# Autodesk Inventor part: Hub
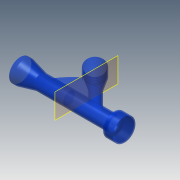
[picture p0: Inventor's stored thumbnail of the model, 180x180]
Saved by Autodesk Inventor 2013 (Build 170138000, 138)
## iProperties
Created: 2013-11
Part Number: Hub
Material: Polycarbonate, Clear
Document SubType Name: Modeling
Designer: Warren
Density: 1 g/cm^3
Author: Warren
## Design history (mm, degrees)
sketch "Sketch1"
  geometry: L1 (0, 0)-(-32.771, 0); L2 (0, 3)-(3, 3); L3 (3, 3)-(7.475, 1.935); L4 (7.475, 1.935)-(27, 1.935); L5 (27, 1.935)-(27, 3); L6 (27, 3)-(30, 3); L7 (30, 3)-(30, 0); L8 (0, 0)-(11.256, 0); L9 (0, 3)-(0, 0); L10 (0, 0)-(30, 0)
  constraints: 20 end point, 4 perpendicular, 3 parallel, 1 collinear, 1 horizontal
  dimensions: "d0" = 3 distance from line of L1 L2.start; "d2" = 30 distance of L6.end L2.start; "d3" = 3 distance of L5.end L6.end; "d4" = 3 distance of L2.start L2.end
revolve "Revolution1" sketch "Sketch1" stored, may be unused: angle "d5" = 90 deg
fillet "Fillet1" dims "d6" = 0.25
sketch "Sketch3"
  geometry: L1 (0, 0)-(43.511, 0); L2 (22, 0)-(8.31, 13.69); L3 (20.939, -1.061)-(15.619, 4.259); L4 (15.619, 4.259)-(11.747, 6.718); L5 (11.747, 6.718)-(9.626, 8.839); L6 (9.626, 8.839)-(11.393, 10.607); L7 (20.939, -1.061)-(22, 0); L8 (11.393, 10.607)-(22, 0)
  constraints: 16 end point, 4 point on line, 2 parallel, 2 perpendicular, 1 collinear, 1 horizontal
  dimensions: "d12" = 45 deg angle of L1 L2; "d13" = 2.5 distance between parallel lines of L2 L5; "d15" = 1.5 distance from line of L2 L3.end; "d16" = 3 distance of L4.end L5.end; "d18" = 15 distance of L2.start L6.end; "d19" = 22 distance of L2.start L1.start
revolve "Revolution2" sketch "Sketch3" stored, may be unused: angle "d17" = 90 deg
shell "Shell2" dims "d20" = 0.25
sketch "Sketch4"
  geometry: L1 (7.475, 1.935)-(27, 1.935) reference; L2 (15.619, 4.259)-(11.747, 6.718) reference; A1 r 19.595 centre (25.045, -8.904) between (12.562, 6.2) and (8.72, 1.935); 1 further point
  constraints: 2 point on circle, 2 point on line, 1 centre point
feature "Rib1" sketch "Sketch4" dims "d21" = 1, "d22" = 1, "d23" = 0, "d24" = 0, "d25" = 1, "d26" = 1
sketch "Sketch5"
  geometry: C1 r 2.75 at (0, 0) reference; C2 r 0.075 at (0, 0)
  constraints: 1 centre point, 1 coincident
  dimensions: "d27" = 0.15 diameter of C2
extrude "Extrusion2" cut sketch "Sketch5" stored distance "d29" = 10; taper "d30" = 0 deg
workplane "Work Plane1"
sketch "Sketch6"
  geometry: C1 r 1.685 at (0, 0) reference; C2 r 0.05 at (0, 0); 1 further point
  constraints: 1 centre point, 1 coincident
  dimensions: "d32" = 0.1 diameter of C2
extrude "Extrusion3" join sketch "Sketch6" stored distance "d34" = 0.25; taper "d35" = 0 deg
thread "Thread1" dims "d36" = 10, "d37" = 0
body "Solid1"
other parameters: "d31" = 15
